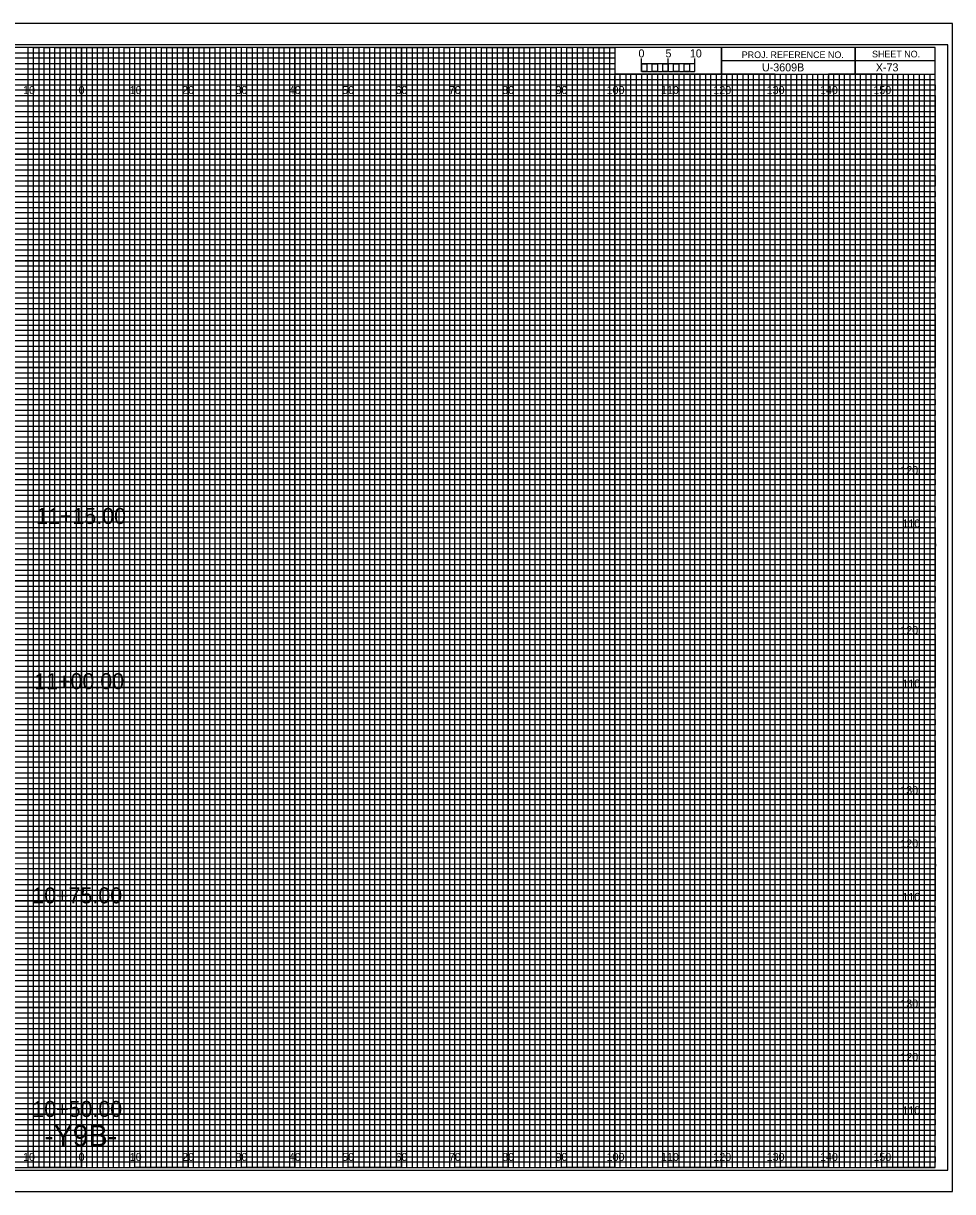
# Model space of a CAD drawing. Extents: x -13 to 323, y -5 to 215.
# Drawn here: x 149.1 to 323.3, y -4.5 to 214.5 of the extents above; entities that cross this region are included whole.
import ezdxf

# ---------------------------------------------------------------- set-up
doc = ezdxf.new("R2010")
doc.units = 0
for name, color, linetype in [('Prop XS Alignment Label', 7, 'Continuous'), ('Prop XS Bar Scale Labels', 7, 'Continuous'), ('Prop XS Elevation Labels', 7, 'Continuous'), ('Prop XS Offset Labels', 7, 'Continuous'), ('Prop XS Project Number', 7, 'Continuous'), ('Prop XS Sheet Number', 7, 'Continuous'), ('Prop XS Station Labels', 7, 'Continuous'), ('Sheet Cross Section CELL', 7, 'Continuous'), ('Sheet Cross Section Grid Major CELL', 7, 'Continuous'), ('Sheet Cross Section Grid Middle CELL', 7, 'Continuous'), ('Sheet Cross Section Grid Minor 1 CELL', 7, 'Continuous'), ('Sheet Cross Section Grid Minor 2 CELL', 7, 'Continuous'), ('Sheet Cross Section Scale CELL', 7, 'Continuous'), ('Sheet Cutting Line CELL', 7, 'Continuous'), ('Sheet DOT Grid CELL', 7, 'Continuous'), ('Sheet Plot Border Inside CELL', 7, 'Continuous'), ('Sheet Plot Border Outside CELL', 7, 'Continuous')]:
    doc.layers.add(name, color=color, linetype=linetype)

msp = doc.modelspace()

# ---------------------------------------------------------------- linework, layer by layer
at = {"layer": 'Sheet Cross Section CELL'}
for p, q in [((305, 210), (305, 205)), ((305, 205), (305, 210)), ((280, 207.5), (280, 205)), ((320, 207.49), (280, 207.49)), ((280, 205), (320, 205))]:
    msp.add_line(p, q, dxfattribs=at)
for points in [[(320, 210), (0, 210), (0, 0), (320, 0)], [(280, 210), (260, 210), (260, 205.03), (280, 205.03)], [(320, 210), (280, 210), (280, 205), (320, 205)]]:
    msp.add_lwpolyline(points, close=True, dxfattribs=at)
at = {"layer": 'Sheet Cross Section Grid Major CELL'}
for p, q in [((150, 210), (140, 210)), ((150, 0), (150, 210)), ((170, 210), (160, 210)), ((160, 210), (160, 0)), ((170, 0), (170, 210)), ((190, 210), (180, 210)), ((180, 210), (180, 0)), ((190, 0), (190, 210)), ((210, 210), (200, 210)), ((200, 210), (200, 0)), ((210, 0), (210, 210)), ((230, 210), (220, 210)), ((220, 210), (220, 0)), ((230, 0), (230, 210)), ((250, 210), (240, 210)), ((240, 210), (240, 0)), ((250, 0), (250, 210)), ((260, 210), (260, 0)), ((270, 0), (270, 205)), ((290, 205), (280, 205)), ((280, 205), (280, 0)), ((290, 0), (290, 205)), ((310, 205), (300, 205)), ((300, 205), (300, 0)), ((310, 0), (310, 205)), ((160, 0), (150, 0)), ((180, 0), (170, 0)), ((200, 0), (190, 0)), ((220, 0), (210, 0)), ((240, 0), (230, 0)), ((260, 0), (250, 0)), ((280, 0), (270, 0)), ((300, 0), (290, 0)), ((320, 0), (310, 0)), ((320, 0), (320, 0))]:
    msp.add_line(p, q, dxfattribs=at)
for points in [[(0, 200), (320, 200), (320, 190), (0, 190)], [(0, 180), (320, 180), (320, 170), (0, 170)], [(0, 160), (320, 160), (320, 150), (0, 150)], [(0, 140), (320, 140), (320, 130), (0, 130)], [(0, 120), (320, 120), (320, 110), (0, 110)], [(0, 100), (320, 100), (320, 90), (0, 90)], [(0, 80), (320, 80), (320, 70), (0, 70)], [(0, 60), (320, 60), (320, 50), (0, 50)], [(0, 40), (320, 40), (320, 30), (0, 30)], [(0, 20), (320, 20), (320, 10), (0, 10)]]:
    msp.add_lwpolyline(points, dxfattribs=at)
at = {"layer": 'Sheet Cross Section Grid Middle CELL'}
for points in [[(145, 0), (155, 0), (155, 210), (165, 210), (165, 0), (175, 0), (175, 210), (185, 210), (185, 0), (195, 0), (195, 210), (205, 210), (205, 0), (215, 0), (215, 210), (225, 210), (225, 0), (235, 0), (235, 210), (245, 210), (245, 0), (255, 0), (255, 210), (259.93, 210), (260, 210), (260, 205), (264.99, 205), (264.99, 0), (275, 0), (275, 205), (285, 205), (285, 0), (295, 0), (295, 205), (305, 205), (305, 0), (315, 0), (315, 205)], [(0, 205), (275, 205)], [(0, 185), (320, 185), (320, 195), (0, 195)], [(0, 165), (320, 165), (320, 175), (0, 175)], [(0, 145), (320, 145), (320, 155), (0, 155)], [(0, 125), (320, 125), (320, 135), (0, 135)], [(0, 105), (320, 105), (320, 115), (0, 115)], [(0, 85), (320, 85), (320, 95), (0, 95)], [(0, 65), (320, 65), (320, 75), (0, 75)], [(0, 45), (320, 45), (320, 55), (0, 55)], [(0, 25), (320, 25), (320, 35), (0, 35)], [(0, 5), (320, 5), (320, 15), (0, 15)]]:
    msp.add_lwpolyline(points, dxfattribs=at)
at = {"layer": 'Sheet Cross Section Grid Minor 1 CELL'}
for p, q in [((0, 209), (260, 209)), ((260, 209), (260, 207.98)), ((260, 207.98), (0, 207.98)), ((0, 207), (260, 207)), ((260, 205.89), (0, 205.89)), ((260, 207), (260, 205.89)), ((0, 204), (320, 204))]:
    msp.add_line(p, q, dxfattribs=at)
for points in [[(0, 203), (270, 203), (320, 203), (320, 202), (0, 202)], [(0, 201), (320, 201), (320, 199), (0, 199)], [(0, 198), (320, 198), (320, 197), (0, 196.98)], [(0, 196), (320, 196), (320, 194), (0, 194)], [(0, 193), (320, 193), (320, 192), (0, 192)], [(0, 191), (320, 191), (320, 189), (0, 189)], [(0, 188), (320, 188), (320, 187), (0, 187)], [(0, 186), (320, 186), (320, 184), (0, 184)], [(0, 183), (320, 183), (320, 182), (0, 182)], [(0, 181), (320, 181), (320, 179), (0, 179)], [(0, 178), (320, 178), (320, 177), (0, 177)], [(0, 176), (320, 176), (320, 173.95), (320, 173), (320, 172), (0, 172)], [(0, 174), (320, 174), (320, 173), (0, 173)], [(0, 171), (320, 171), (320, 169), (0, 169.03)], [(0, 169.03), (320, 169), (320, 168), (0, 168)], [(0, 167), (320, 167), (320, 166), (0, 166)], [(0, 164), (320, 164), (320, 163), (0, 163)], [(0, 162), (320, 162), (320, 161), (0, 161)], [(-0.07, 158.89), (320, 158.89), (320, 157.88), (-0.07, 157.88)], [(0, 157), (320, 157), (320, 156), (0, 156)], [(0, 154), (320, 154), (320, 153), (0, 153)], [(0, 152), (320, 152), (320, 151), (0, 151)], [(0, 149), (320, 149), (320, 148), (0, 148)], [(0, 147), (320, 147), (320, 146), (0, 146)], [(0, 144), (320, 144), (320, 143), (0, 143)], [(0, 142), (320, 142), (320, 141), (0, 141)], [(0, 139), (320, 139), (319.99, 137.98), (0, 138)], [(0, 137), (320, 137), (320, 136), (0, 136)], [(0, 134), (320, 134), (320, 133), (0, 133)], [(0, 132), (320, 132), (320, 131), (0, 131)], [(0, 129), (320, 129), (320, 128), (0, 128)], [(0, 127), (320, 127), (320, 126), (0, 126)], [(0, 124), (320, 124), (320, 123), (0, 123)], [(0, 122), (320, 122), (320, 121), (0, 121)], [(0, 119), (320, 119), (320, 118), (0, 118)], [(0, 116.99), (320.07, 116.91), (320, 116), (0, 116)], [(0, 114), (320, 114), (320, 113), (0, 113)], [(0, 112), (320, 112), (320, 111), (0, 111)], [(0, 109), (320, 109), (320, 108), (0, 108)], [(0, 107), (320, 107), (320, 106), (0, 106)], [(0, 104), (320, 104), (320, 103), (0, 103)], [(0, 102), (320, 102), (320, 101), (0, 101)], [(0, 99), (320, 99), (320, 98), (0, 98)], [(0, 97), (320, 97), (320, 96), (0, 96)], [(0, 94), (320, 94), (320, 93), (0, 93)], [(0, 92), (320, 92), (320, 91), (0, 91)], [(0, 89), (320, 89), (320, 88), (0, 88)], [(0, 87), (320, 87), (320, 86), (0, 86)], [(0, 84), (320, 84), (320, 83), (0, 83)], [(0, 82), (320, 82), (320, 81), (0, 81)], [(0, 79), (320, 79), (319.99, 77.98), (0, 78)], [(0, 77), (320, 77), (320, 76), (0, 76)], [(0, 74), (320, 74), (320, 73), (0, 73)], [(0, 72), (320, 72), (320, 71), (0, 71)], [(0, 69), (320, 69), (320, 68), (0, 68)], [(0, 67), (320, 67), (320, 66), (0, 66)], [(0, 64), (320, 64), (320, 63), (0, 63)], [(0, 62), (320, 62), (320, 61), (0, 61)], [(0, 59), (320, 59), (320, 58), (0, 58)], [(0, 56.99), (320.07, 56.91), (320, 56), (0, 56)], [(0, 54), (320, 54), (320, 53), (0, 53)], [(0, 52), (320, 52), (320, 51), (0, 51)], [(0, 49), (320, 49), (320, 48), (0, 48)], [(0, 47), (320, 47), (320, 46), (0, 46)], [(0, 44), (320, 44), (320, 43), (0, 43)], [(0, 42), (320, 42), (320, 41), (0, 41)], [(0, 39), (320, 39), (320, 38), (0, 38)], [(0, 37), (320, 37), (320, 36), (0, 36)], [(0, 34), (320, 34), (320, 33), (0, 33)], [(0, 32), (320, 32), (320, 31), (0, 31)], [(0, 29), (320, 29), (320, 28), (0, 28)], [(0, 27), (320, 27), (320, 26), (0, 26)], [(0, 24), (320, 24), (320, 23), (0, 23)], [(0, 22), (320, 22), (320, 21), (0, 21)], [(0, 19), (320, 19), (320, 18), (0, 18)], [(0, 17), (320, 17), (320, 16), (0, 16)], [(0, 14), (320, 14), (320, 13), (0, 13)], [(0, 12), (320, 12), (320, 11), (0, 11)], [(0, 9), (320, 9), (320, 8), (0, 8)], [(0, 7), (320, 7), (320, 6), (0, 6)], [(0, 4), (320, 4), (320, 3), (0, 3)], [(0, 2), (320, 2), (320, 1), (0, 1)]]:
    msp.add_lwpolyline(points, dxfattribs=at)
at = {"layer": 'Sheet Cross Section Grid Minor 2 CELL'}
for p, q in [((267, 205), (266.01, 205)), ((266.01, 205), (266.01, 0)), ((267, 0), (267, 205)), ((269, 205), (268, 205)), ((268, 205), (268, 0)), ((269, 0), (269, 205)), ((266.01, 0), (265, 0)), ((268, 0), (267, 0))]:
    msp.add_line(p, q, dxfattribs=at)
for points in [[(150, 0), (151, 0), (151, 210), (152, 210), (152, 0)], [(152, 0), (153, 0), (153, 210), (154, 210), (154, 0)], [(155, 0), (156, 0), (156, 210), (157, 210), (157, 0)], [(157, 0), (158, 0), (158, 210), (159, 210), (159, 0)], [(160, 0), (161, 0), (161, 210), (162, 210), (162, 0)], [(162, 0), (163, 0), (163, 210), (164, 210), (164, 0)], [(165, 0), (166, 0), (166, 210), (167, 210), (167, 0)], [(167, 0), (168, 0), (168, 210), (169, 210), (169, 0)], [(170, 0), (171, 0), (171, 210), (172, 210), (172, 0)], [(172, 0), (173, 0), (173, 210), (174, 210), (174, 0)], [(175, 0), (176, 0), (176, 210), (177, 210), (177, 0)], [(177, 0), (178, 0), (178, 210), (179, 210), (179, 0)], [(180, 0), (181, 0), (181, 210), (182, 210), (182, 0)], [(182, 0), (183, 0), (183, 210), (184, 210), (184, 0)], [(185, 0), (186, 0), (186, 210), (187, 210), (187, 0)], [(187, 0), (188, 0), (188, 210), (189, 210), (189, 0)], [(190, 0), (191, 0), (191, 210), (192, 210), (192, 0)], [(192, 0), (193, 0), (193, 210), (194, 210), (194, 0)], [(195, 0), (196, 0), (196, 210), (197, 210), (197, 0)], [(197, 0), (198, 0), (198, 210), (199, 210), (199, 0)], [(200, 0), (201, 0), (201, 210), (202, 210), (202, 0)], [(202, 0), (203, 0), (203, 210), (204, 210), (204, 0)], [(205, 0), (206, 0), (206, 210), (207, 210), (207, 0)], [(207, 0), (208, 0), (208, 210), (209, 210), (209, 0)], [(210, 0), (211, 0), (211, 210), (212, 210), (212, 0)], [(212, 0), (213, 0), (213, 210), (214, 210), (214, 0)], [(215, 0), (216, 0), (216, 210), (217, 210), (217, 0)], [(217, 0), (218, 0), (218, 210), (219, 210), (219, 0)], [(220, 0), (221, 0), (221, 210), (222, 210), (222, 0)], [(222, 0), (223, 0), (223, 210), (224, 210), (224, 0)], [(225, 0), (226, 0), (226, 210), (227, 210), (227, 0)], [(227, 0), (228, 0), (228, 210), (229, 210), (229, 0)], [(230, 0), (231, 0), (231, 210), (232, 210), (232, 0)], [(232, 0), (233, 0), (233, 210), (234, 210), (234, 0)], [(235, 0), (236, 0), (236, 210), (237, 210), (237, 0)], [(237, 0), (238, 0), (238, 210), (239, 210), (239, 0)], [(240, 0), (241, 0), (241, 210), (242, 210), (242, 0)], [(242, 0), (243, 0), (243, 210), (244, 210), (244, 0)], [(245, 0), (246, 0), (246, 210), (247, 210), (247, 0)], [(247, 0), (248, 0), (248, 210), (249, 210), (249, 0)], [(250, 0), (251, 0), (251, 210), (252, 210), (252, 0)], [(252, 0), (253, 0), (253, 210), (254, 210), (254, 0)], [(255, 0), (256, 0), (256, 210), (257, 210), (257, 0)], [(257, 0), (258, 0), (258, 210), (259, 210), (259, 0)], [(260, 0), (261, 0), (261, 205), (262.02, 205), (262.02, 0)], [(262, 0), (263, 0), (263, 205), (263.99, 205), (263.99, 0)], [(270, 0), (270.98, 0), (270.98, 205), (272, 205), (272, 0)], [(272, 0), (273, 0), (273, 205), (274.05, 205), (274.05, 0)], [(275, 0), (276, 0), (276, 205), (277, 205), (277, 0)], [(277, 0), (278, 0), (278, 205), (279, 205), (279, 0)], [(280, 0), (281, 0), (281, 205), (282, 205), (282, 0)], [(282, 0), (283, 0), (283, 205), (284, 205), (284, 0)], [(285, 0), (286, 0), (286, 205), (287, 205), (287, 0)], [(287, 0), (288, 0), (288, 205), (289, 205), (289, 0)], [(290, 0), (291, 0), (291, 205), (292, 205), (292, 0)], [(292, 0), (293, 0), (293, 205), (294, 205), (294, 0)], [(295, 0), (296, 0), (296, 205), (297, 205), (297, 0)], [(297, 0), (298, 0), (298, 205), (299, 205), (299, 0)], [(300, 0), (301, 0), (301, 205), (302, 205), (302, 0)], [(302, 0), (303, 0), (303, 205), (304, 205), (304, 0)], [(305, 0), (306, 0), (306, 205), (307, 205), (307, 0)], [(307, 0), (308, 0), (308, 205), (309, 205), (309, 0)], [(310, 0), (311, 0), (311, 205), (312, 205), (312, 0)], [(312, 0), (313, 0), (313, 205), (314, 205), (314, 0)], [(315, 0), (316, 0), (316, 205), (317, 205), (317, 0)], [(317, 0), (318, 0), (318, 205), (319, 205), (319, 0)]]:
    msp.add_lwpolyline(points, dxfattribs=at)
at = {"layer": 'Sheet Cross Section Scale CELL'}
for p, q in [((265, 205.49), (265, 207.9)), ((265, 206.9), (265, 207.9)), ((270, 205.49), (270, 207.9)), ((275, 205.49), (275, 207.9)), ((275, 206.9), (275, 207.9))]:
    msp.add_line(p, q, dxfattribs=at)
for points in [[(275, 206.9), (265, 206.9), (265, 205.49), (275, 205.49)], [(265, 206.9), (266, 206.9), (266, 205.49), (265, 205.49)], [(267, 206.9), (268, 206.9), (268, 205.49), (267, 205.49)], [(269, 206.9), (270, 206.9), (270, 205.49), (269, 205.49)], [(271, 206.9), (272, 206.9), (272, 205.49), (271, 205.49)], [(273, 206.9), (274, 206.9), (274, 205.49), (273, 205.49)]]:
    msp.add_lwpolyline(points, close=True, dxfattribs=at)
at = {"layer": 'Sheet Cutting Line CELL'}
for p, q in [((323.3, 214.5), (-13.4, 214.5)), ((-13.4, -4.5), (323.3, -4.5))]:
    msp.add_line(p, q, dxfattribs=at)
at = {"layer": 'Sheet DOT Grid CELL'}
for p, q in [((150, 0), (150, 210)), ((160, 0), (160, 210)), ((170, 0), (170, 210)), ((180, 0), (180, 210)), ((190, 0), (190, 210)), ((200, 0), (200, 210)), ((210, 0), (210, 210)), ((220, 0), (220, 210)), ((230, 0), (230, 210)), ((240, 0), (240, 210)), ((250, 0), (250, 210)), ((260, 0), (260, 204.69)), ((270, 0), (270, 204.69)), ((280, 0), (280, 204.69)), ((290, 0), (290, 204.69)), ((300, 0), (300, 204.69)), ((310, 0), (310, 204.69)), ((0, 200), (320, 200)), ((0, 190), (320, 190)), ((0, 180), (320, 180)), ((0, 170), (320, 170)), ((0, 160), (320, 160)), ((0, 150), (320, 150)), ((0, 140), (320, 140)), ((0, 130), (320, 130)), ((0, 120), (320, 120)), ((0, 110), (320, 110)), ((0, 100), (320, 100)), ((0, 90), (320, 90)), ((0, 80), (320, 80)), ((0, 70), (320, 70)), ((0, 60), (320, 60)), ((0, 50), (320, 50)), ((0, 40), (320, 40)), ((0, 30), (320, 30)), ((0, 20), (320, 20)), ((0, 10), (320, 10))]:
    msp.add_line(p, q, dxfattribs=at)
at = {"layer": 'Sheet Plot Border Inside CELL'}
msp.add_lwpolyline([(-10.8, -0.5), (322.4, -0.5), (322.4, 210.5), (-10.8, 210.5)], close=True, dxfattribs=at)
at = {"layer": 'Sheet Plot Border Outside CELL'}
msp.add_lwpolyline([(-13.4, -4.5), (323.3, -4.5), (323.3, 214.5), (-13.4, 214.5)], close=True, dxfattribs=at)

# ---------------------------------------------------------------- texts
at = {"layer": 'Prop XS Alignment Label'}
msp.add_text('-Y9B-', height=4, dxfattribs=at).set_placement((153.01, 4))
at = {"layer": 'Prop XS Bar Scale Labels'}
for s, p in [('5', (269.47, 208.12)), ('10', (274.04, 208.12))]:
    msp.add_text(s, height=1.5, dxfattribs=at).set_placement(p)
at = {"layer": 'Prop XS Elevation Labels'}
for s, p in [('120', (313.5, 130)), ('110', (313.88, 120)), ('120', (313.5, 100)), ('110', (313.88, 90)), ('130', (313.49, 70)), ('120', (313.5, 60)), ('110', (313.88, 50)), ('130', (313.49, 30)), ('120', (313.5, 20)), ('110', (313.88, 10))]:
    msp.add_text(s, height=1.5, dxfattribs=at).set_placement(p)
at = {"layer": 'Prop XS Offset Labels'}
for s, p in [('10', (149.04, 201.25)), ('0', (159.45, 201.25)), ('0', (159.45, 201.25)), ('10', (169.04, 201.25)), ('20', (178.86, 201.25)), ('30', (188.86, 201.25)), ('40', (198.86, 201.25)), ('50', (208.86, 201.25)), ('60', (218.86, 201.25)), ('70', (228.86, 201.25)), ('80', (238.86, 201.25)), ('90', (248.86, 201.25)), ('100', (258.44, 201.25)), ('110', (268.62, 201.25)), ('120', (278.44, 201.25)), ('130', (288.44, 201.25)), ('140', (298.44, 201.25)), ('150', (308.44, 201.25)), ('10', (149.04, 1.25)), ('0', (159.45, 1.25)), ('0', (159.45, 1.25)), ('10', (169.04, 1.25)), ('20', (178.86, 1.25)), ('30', (188.86, 1.25)), ('40', (198.86, 1.25)), ('50', (208.86, 1.25)), ('60', (218.86, 1.25)), ('70', (228.86, 1.25)), ('80', (238.86, 1.25)), ('90', (248.86, 1.25)), ('100', (258.44, 1.25)), ('110', (268.62, 1.25)), ('120', (278.44, 1.25)), ('130', (288.44, 1.25)), ('140', (298.44, 1.25)), ('150', (308.44, 1.25))]:
    msp.add_text(s, height=1.5, dxfattribs=at).set_placement(p)
at = {"layer": 'Prop XS Project Number'}
msp.add_text('U-3609B', height=1.5, dxfattribs=at).set_placement((287.56, 205.5))
at = {"layer": 'Prop XS Sheet Number'}
msp.add_text('X-73', height=1.5, dxfattribs=at).set_placement((308.9, 205.5))
at = {"layer": 'Prop XS Station Labels'}
for s, p in [('11+15.00', (151.49, 120.66)), ('11+00.00', (151.13, 89.69)), ('10+75.00', (150.77, 49.54)), ('10+50.00', (150.77, 9.5))]:
    msp.add_text(s, height=3, dxfattribs=at).set_placement(p)
at = {"layer": 'Sheet Cross Section CELL'}
for s, p in [('PROJ. REFERENCE NO.', (283.77, 207.99)), ('SHEET NO.', (308.19, 208.12))]:
    msp.add_text(s, height=1.25, dxfattribs=at).set_placement(p)
at = {"layer": 'Sheet Cross Section Scale CELL'}
msp.add_text('0', height=1.5, dxfattribs=at).set_placement((264.41, 208.12))

doc.saveas('drawing.dxf')
